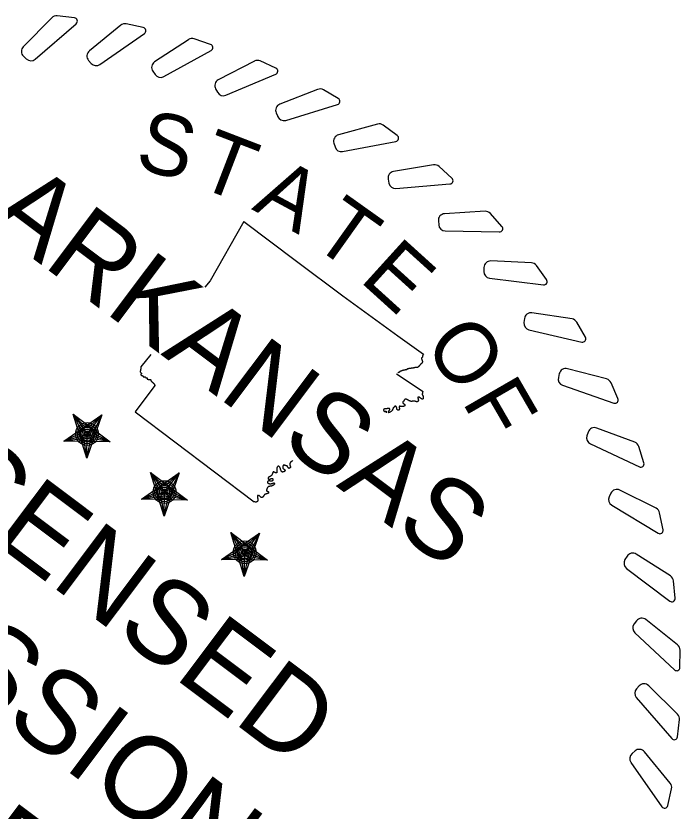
# Model space of a CAD drawing. Extents: x 627721 to 628787, y 367711 to 368404.
# Drawn here: x 628750.25 to 628786.81, y 368199.73 to 368243.51 of the extents above; entities that cross this region are included whole.
import ezdxf

# ---------------------------------------------------------------- set-up
doc = ezdxf.new("R2010")
doc.units = 0
doc.layers.add('R_Border PE-PDH', color=7, linetype='Continuous')

msp = doc.modelspace()

# ---------------------------------------------------------------- linework, layer by layer
at = {"layer": 'R_Border PE-PDH'}
for p, q in [((628771.211, 368223.811), (628772.624, 368222.86)), ((628753.402, 368221.577), (628754.176, 368220.489)), ((628753.402, 368221.577), (628754.041, 368220.892)), ((628753.402, 368221.577), (628753.826, 368220.703)), ((628754.176, 368220.489), (628754.975, 368221.553)), ((628754.975, 368221.553), (628754.304, 368220.909)), ((628754.975, 368221.553), (628754.571, 368220.717)), ((628752.896, 368220.096), (628753.798, 368220.532)), ((628755.431, 368220.053), (628754.49, 368220.537)), ((628752.896, 368220.096), (628754.176, 368220.489)), ((628752.896, 368220.096), (628753.995, 368220.261)), ((628754.147, 368219.157), (628753.989, 368220.252)), ((628754.147, 368219.157), (628754.176, 368220.489)), ((628754.147, 368219.157), (628754.385, 368220.306)), ((628755.431, 368220.053), (628754.176, 368220.489)), ((628755.431, 368220.053), (628754.613, 368220.203)), ((628757.662, 368218.378), (628758.436, 368217.291)), ((628757.662, 368218.378), (628758.301, 368217.693)), ((628757.662, 368218.378), (628758.085, 368217.504)), ((628758.436, 368217.291), (628759.235, 368218.355)), ((628759.235, 368218.355), (628758.564, 368217.71)), ((628759.235, 368218.355), (628758.831, 368217.519)), ((628757.156, 368216.898), (628758.058, 368217.333)), ((628757.156, 368216.898), (628758.436, 368217.291)), ((628757.156, 368216.898), (628758.255, 368217.062)), ((628758.407, 368215.959), (628758.249, 368217.053)), ((628758.407, 368215.959), (628758.436, 368217.291)), ((628758.407, 368215.959), (628758.644, 368217.107)), ((628759.691, 368216.855), (628758.436, 368217.291)), ((628759.691, 368216.855), (628758.75, 368217.338)), ((628759.691, 368216.855), (628758.873, 368217.004)), ((628762.079, 368215.061), (628762.854, 368213.973)), ((628762.079, 368215.061), (628762.718, 368214.376)), ((628762.079, 368215.061), (628762.503, 368214.186)), ((628762.854, 368213.973), (628763.653, 368215.037)), ((628763.653, 368215.037), (628762.982, 368214.392)), ((628763.653, 368215.037), (628763.248, 368214.201)), ((628761.574, 368213.58), (628762.475, 368214.016)), ((628761.574, 368213.58), (628762.854, 368213.973)), ((628762.825, 368212.641), (628762.854, 368213.973)), ((628764.108, 368213.537), (628762.854, 368213.973)), ((628764.108, 368213.537), (628763.167, 368214.021)), ((628761.574, 368213.58), (628762.673, 368213.744)), ((628762.825, 368212.641), (628762.666, 368213.736)), ((628762.825, 368212.641), (628763.062, 368213.789)), ((628764.108, 368213.537), (628763.29, 368213.687))]:
    msp.add_line(p, q, dxfattribs=at)
for points in [[(628752.224, 368243.404), (628750.656, 368241.816)], [(628753.47, 368243.405), (628752.525, 368243.511)], [(628751.314, 368241.134), (628753.569, 368243.085)], [(628756.018, 368243.001), (628754.293, 368241.586)], [(628757.257, 368242.872), (628756.328, 368243.076)], [(628754.875, 368240.839), (628757.322, 368242.543)], [(628759.749, 368242.204), (628757.885, 368240.977)], [(628760.967, 368241.946), (628760.065, 368242.246)], [(628758.386, 368240.173), (628760.998, 368241.612)], [(628750.666, 368241.293), (628750.824, 368241.144)], [(628754.247, 368241.065), (628754.389, 368240.9)], [(628763.376, 368241.022), (628761.394, 368239.996)], [(628764.561, 368240.637), (628763.695, 368241.03)], [(628757.785, 368240.463), (628757.909, 368240.285)], [(628761.808, 368239.144), (628764.556, 368240.302)], [(628761.241, 368239.495), (628761.345, 368239.305)], [(628766.859, 368239.466), (628764.781, 368238.653)], [(628767.998, 368238.96), (628767.178, 368239.441)], [(628765.104, 368237.762), (628767.958, 368238.627)], [(628764.577, 368238.171), (628764.661, 368237.971)], [(628770.161, 368237.555), (628768.009, 368236.964)], [(628771.24, 368236.933), (628770.475, 368237.497)], [(628767.756, 368236.506), (628767.818, 368236.298)], [(628768.238, 368236.044), (628771.166, 368236.606)], [(628773.245, 368235.309), (628771.043, 368234.946)], [(628774.253, 368234.578), (628773.551, 368235.219)], [(628770.743, 368234.517), (628770.784, 368234.304)], [(628771.174, 368234.008), (628774.145, 368234.26)], [(628776.077, 368232.754), (628773.85, 368232.623)], [(628777.004, 368231.921), (628776.372, 368232.631)], [(628762.801, 368232.186), (628760.936, 368228.93), (628760.655, 368228.581)], [(628762.801, 368232.186), (628765.697, 368230.009), (628768.243, 368228.105), (628771.277, 368225.899), (628772.692, 368224.887)], [(628773.507, 368232.227), (628773.524, 368232.011)], [(628773.882, 368231.676), (628776.863, 368231.616)], [(628778.627, 368229.916), (628776.398, 368230.018)], [(628779.461, 368228.99), (628778.908, 368229.763)], [(628776.015, 368229.661), (628776.011, 368229.444)], [(628776.331, 368229.073), (628779.29, 368228.702)], [(628780.866, 368226.827), (628778.66, 368227.162)], [(628778.242, 368226.847), (628778.215, 368226.632)], [(628781.599, 368225.82), (628781.129, 368226.646)], [(628778.495, 368226.229), (628781.398, 368225.551)], [(628757.672, 368224.871), (628757.124, 368224.19)], [(628782.77, 368223.521), (628780.611, 368224.085)], [(628780.163, 368223.815), (628780.113, 368223.604)], [(628757.898, 368223.157), (628756.813, 368221.705), (628763.372, 368216.763)], [(628780.349, 368223.174), (628783.166, 368222.196)], [(628783.394, 368222.442), (628783.013, 368223.314)], [(628754.975, 368221.553), (628754.147, 368219.157), (628753.402, 368221.577), (628755.431, 368220.053), (628752.896, 368220.096), (628754.975, 368221.553)], [(628781.756, 368220.599), (628781.684, 368220.394)], [(628784.318, 368220.034), (628782.23, 368220.821)], [(628781.874, 368219.942), (628784.573, 368218.675)], [(628784.826, 368218.896), (628784.538, 368219.802)], [(628759.235, 368218.355), (628758.407, 368215.959), (628757.662, 368218.378), (628759.691, 368216.855), (628757.156, 368216.898), (628759.235, 368218.355)], [(628783.004, 368217.234), (628782.911, 368217.038)], [(628785.493, 368216.405), (628783.499, 368217.405)], [(628783.053, 368216.569), (628785.605, 368215.027)], [(628785.879, 368215.22), (628785.688, 368216.151)], [(628763.653, 368215.037), (628762.825, 368212.641), (628762.079, 368215.061), (628764.108, 368213.537), (628761.574, 368213.58), (628763.653, 368215.037)], [(628783.893, 368213.757), (628783.781, 368213.572)], [(628786.282, 368212.672), (628784.403, 368213.876)], [(628783.873, 368213.09), (628786.25, 368211.29)], [(628786.542, 368211.454), (628786.449, 368212.4)], [(628784.414, 368210.207), (628784.283, 368210.034)], [(628786.677, 368208.878), (628784.934, 368210.271)], [(628784.324, 368209.546), (628786.5, 368207.506)], [(628786.808, 368207.639), (628786.815, 368208.589)], [(628784.562, 368206.621), (628784.413, 368206.463)], [(628786.673, 368205.063), (628785.085, 368206.63)], [(628784.403, 368205.973), (628786.354, 368203.717)], [(628786.674, 368203.817), (628786.78, 368204.762)], [(628784.333, 368203.039), (628784.169, 368202.898)], [(628786.27, 368201.269), (628784.855, 368202.994)], [(628784.108, 368202.411), (628785.812, 368199.965)], [(628786.141, 368200.03), (628786.345, 368200.958)]]:
    msp.add_lwpolyline(points, dxfattribs=at)
for centre, radius in [((628754.171, 368220.489), 0.628), ((628754.171, 368220.489), 0.527), ((628754.171, 368220.489), 0.422), ((628754.171, 368220.489), 0.361), ((628754.171, 368220.489), 0.272), ((628754.171, 368220.489), 0.181), ((628754.171, 368220.489), 0.108), ((628758.431, 368217.29), 0.628), ((628758.431, 368217.29), 0.527), ((628758.431, 368217.29), 0.422), ((628758.431, 368217.29), 0.361), ((628758.431, 368217.29), 0.272), ((628758.431, 368217.29), 0.181), ((628758.431, 368217.29), 0.108), ((628762.849, 368213.973), 0.628), ((628762.849, 368213.973), 0.527), ((628762.849, 368213.973), 0.422), ((628762.849, 368213.973), 0.361), ((628762.849, 368213.973), 0.272), ((628762.849, 368213.973), 0.181), ((628762.849, 368213.973), 0.108)]:
    msp.add_circle(centre, radius, dxfattribs=at)
for centre, radius, start, end in [((628752.484, 368243.147), 0.366, 83.609, 135.3653), ((628753.45, 368243.223), 0.183, 310.8578, 83.609), ((628756.25, 368242.719), 0.366, 77.609, 129.3653), ((628757.218, 368242.693), 0.183, 304.8578, 77.609), ((628759.95, 368241.899), 0.366, 71.609, 123.3653), ((628750.917, 368241.559), 0.366, 135.3653, 226.7231), ((628754.525, 368241.303), 0.366, 129.3653, 220.7231), ((628760.91, 368241.772), 0.183, 298.8578, 71.609), ((628751.074, 368241.411), 0.366, 226.7231, 310.8578), ((628754.666, 368241.139), 0.366, 220.7231, 304.8578), ((628758.086, 368240.671), 0.366, 123.3653, 214.7231), ((628763.544, 368240.697), 0.366, 65.609, 117.3653), ((628758.21, 368240.493), 0.366, 214.7231, 298.8578), ((628764.485, 368240.471), 0.183, 292.8578, 65.609), ((628761.562, 368239.671), 0.366, 117.3653, 208.7231), ((628766.992, 368239.125), 0.366, 59.609, 111.3653), ((628761.666, 368239.481), 0.366, 208.7231, 292.8578), ((628767.905, 368238.802), 0.183, 286.8578, 59.609), ((628764.914, 368238.312), 0.366, 111.3653, 202.7231), ((628764.998, 368238.113), 0.366, 202.7231, 286.8578), ((628770.258, 368237.202), 0.366, 53.609, 105.3653), ((628768.106, 368236.611), 0.366, 105.3653, 196.7231), ((628771.132, 368236.786), 0.183, 280.8578, 53.609), ((628768.169, 368236.403), 0.366, 196.7231, 280.8578), ((628773.305, 368234.948), 0.366, 47.609, 99.3653), ((628771.103, 368234.585), 0.366, 99.3653, 190.7231), ((628774.13, 368234.443), 0.183, 274.8578, 47.609), ((628771.143, 368234.372), 0.366, 190.7231, 274.8578), ((628773.871, 368232.257), 0.366, 93.3653, 184.7231), ((628776.099, 368232.388), 0.366, 41.609, 93.3653), ((628773.889, 368232.041), 0.366, 184.7231, 268.8578), ((628776.867, 368231.799), 0.183, 268.8578, 41.609), ((628776.381, 368229.653), 0.366, 87.3653, 178.7231), ((628778.61, 368229.55), 0.366, 35.609, 87.3653), ((628776.376, 368229.436), 0.366, 178.7231, 262.8578), ((628779.313, 368228.884), 0.183, 262.8578, 35.609), ((628778.605, 368226.8), 0.366, 81.3653, 172.7231), ((628780.811, 368226.465), 0.366, 29.609, 81.3653), ((628778.578, 368226.585), 0.366, 172.7231, 256.8578), ((628781.44, 368225.729), 0.183, 256.8578, 29.609), ((628780.519, 368223.731), 0.366, 75.3653, 166.7231), ((628780.469, 368223.52), 0.366, 166.7231, 250.8578), ((628782.678, 368223.167), 0.366, 23.609, 75.3653), ((628783.226, 368222.369), 0.183, 250.8578, 23.609), ((628782.101, 368220.478), 0.366, 69.3653, 160.7231), ((628782.029, 368220.274), 0.366, 160.7231, 244.8578), ((628784.189, 368219.692), 0.366, 17.609, 69.3653), ((628784.651, 368218.841), 0.183, 244.8578, 17.609), ((628783.335, 368217.078), 0.366, 63.3653, 154.7231), ((628783.242, 368216.882), 0.366, 154.7231, 238.8578), ((628785.329, 368216.078), 0.366, 11.609, 63.3653), ((628785.7, 368215.183), 0.183, 238.8578, 11.609), ((628784.093, 368213.382), 0.366, 148.7231, 232.8578), ((628784.206, 368213.567), 0.366, 57.3653, 148.7231), ((628786.085, 368212.364), 0.366, 5.609, 57.3653), ((628786.36, 368211.436), 0.183, 232.8578, 5.609), ((628784.574, 368209.813), 0.366, 142.7231, 226.8578), ((628784.706, 368209.985), 0.366, 51.3653, 142.7231), ((628786.449, 368208.592), 0.366, 359.609, 51.3653), ((628786.625, 368207.64), 0.183, 226.8578, 359.609), ((628784.828, 368206.37), 0.366, 45.3653, 136.7231), ((628784.68, 368206.212), 0.366, 136.7231, 220.8578), ((628786.416, 368204.802), 0.366, 353.609, 45.3653), ((628786.492, 368203.837), 0.183, 220.8578, 353.609), ((628784.572, 368202.762), 0.366, 39.3653, 130.7231), ((628784.408, 368202.621), 0.366, 130.7231, 214.8578), ((628785.987, 368201.037), 0.366, 347.609, 39.3653), ((628785.962, 368200.069), 0.183, 214.8578, 347.609)]:
    msp.add_arc(centre, radius, start, end, dxfattribs=at)
for points in [[(628772.692, 368224.887), (628772.674, 368224.86), (628772.657, 368224.831), (628772.642, 368224.802), (628772.632, 368224.784), (628772.641, 368224.76), (628772.636, 368224.742), (628772.627, 368224.713), (628772.587, 368224.696), (628772.583, 368224.664), (628772.581, 368224.645), (628772.584, 368224.627), (628772.589, 368224.609), (628772.596, 368224.584), (628772.61, 368224.563), (628772.617, 368224.538), (628772.625, 368224.509), (628772.63, 368224.482), (628772.625, 368224.451), (628772.62, 368224.423), (628772.607, 368224.4), (628772.59, 368224.382), (628772.571, 368224.363), (628772.546, 368224.35), (628772.528, 368224.33), (628772.509, 368224.308), (628772.492, 368224.284), (628772.472, 368224.262), (628772.455, 368224.244), (628772.437, 368224.225), (628772.419, 368224.207), (628772.403, 368224.19), (628772.388, 368224.172), (628772.367, 368224.159), (628772.343, 368224.146), (628772.316, 368224.148), (628772.29, 368224.147), (628772.268, 368224.146), (628772.247, 368224.147), (628772.225, 368224.146), (628772.203, 368224.144), (628772.181, 368224.141), (628772.159, 368224.136), (628772.139, 368224.132), (628772.122, 368224.119), (628772.102, 368224.117), (628772.076, 368224.114), (628772.05, 368224.112), (628772.023, 368224.109), (628771.997, 368224.106), (628771.97, 368224.103), (628771.943, 368224.099), (628771.921, 368224.096), (628771.898, 368224.092), (628771.876, 368224.088), (628771.85, 368224.083), (628771.825, 368224.075), (628771.801, 368224.066), (628771.778, 368224.058), (628771.765, 368224.029), (628771.741, 368224.024), (628771.718, 368224.019), (628771.694, 368224.02), (628771.67, 368224.016), (628771.651, 368224.012), (628771.631, 368224.008), (628771.611, 368224.004), (628771.585, 368223.999), (628771.558, 368223.993), (628771.532, 368223.988), (628771.51, 368223.983), (628771.494, 368223.964), (628771.474, 368223.956), (628771.448, 368223.944), (628771.417, 368223.944), (628771.391, 368223.931), (628771.371, 368223.921), (628771.361, 368223.895), (628771.342, 368223.884), (628771.324, 368223.874), (628771.301, 368223.87), (628771.283, 368223.861), (628771.28, 368223.86), (628771.274, 368223.859), (628771.275, 368223.855)], [(628757.124, 368224.19), (628757.137, 368224.15), (628757.132, 368224.118), (628757.125, 368224.083), (628757.12, 368224.061), (628757.115, 368224.04), (628757.11, 368224.018), (628757.104, 368223.99), (628757.097, 368223.962), (628757.094, 368223.933), (628757.091, 368223.911), (628757.109, 368223.892), (628757.119, 368223.874), (628757.13, 368223.855), (628757.154, 368223.844), (628757.165, 368223.826), (628757.177, 368223.804), (628757.115, 368223.778), (628757.13, 368223.757), (628757.143, 368223.739), (628757.163, 368223.725), (628757.182, 368223.715), (628757.198, 368223.706), (628757.219, 368223.704), (628757.235, 368223.695), (628757.256, 368223.683), (628757.261, 368223.648), (628757.282, 368223.634), (628757.307, 368223.618), (628757.351, 368223.646), (628757.377, 368223.63), (628757.389, 368223.623), (628757.392, 368223.601), (628757.404, 368223.593), (628757.422, 368223.58), (628757.456, 368223.588), (628757.472, 368223.575), (628757.487, 368223.563), (628757.47, 368223.52), (628757.488, 368223.513), (628757.514, 368223.504), (628757.548, 368223.495), (628757.577, 368223.491), (628757.606, 368223.487), (628757.643, 368223.493), (628757.668, 368223.485), (628757.691, 368223.476), (628757.678, 368223.422), (628757.697, 368223.404), (628757.712, 368223.389), (628757.732, 368223.373), (628757.748, 368223.357), (628757.768, 368223.337), (628757.788, 368223.318), (628757.808, 368223.298), (628757.823, 368223.283), (628757.843, 368223.272), (628757.857, 368223.255), (628757.872, 368223.239), (628757.877, 368223.217), (628757.886, 368223.197), (628757.894, 368223.181), (628757.907, 368223.144), (628757.903, 368223.148), (628757.902, 368223.149), (628757.9, 368223.154), (628757.898, 368223.157)], [(628772.603, 368222.873), (628772.609, 368222.868), (628772.618, 368222.866), (628772.624, 368222.86), (628772.649, 368222.832), (628772.638, 368222.787), (628772.636, 368222.749), (628772.635, 368222.724), (628772.621, 368222.701), (628772.623, 368222.676), (628772.624, 368222.654), (628772.631, 368222.635), (628772.639, 368222.615), (628772.647, 368222.597), (628772.667, 368222.585), (628772.672, 368222.566), (628772.678, 368222.544), (628772.676, 368222.522), (628772.675, 368222.499), (628772.674, 368222.477), (628772.671, 368222.456), (628772.665, 368222.437), (628772.66, 368222.421), (628772.642, 368222.404), (628772.623, 368222.407), (628772.599, 368222.409), (628772.588, 368222.431), (628772.57, 368222.441), (628772.549, 368222.452), (628772.528, 368222.462), (628772.507, 368222.474), (628772.488, 368222.484), (628772.478, 368222.509), (628772.455, 368222.516), (628772.431, 368222.523), (628772.393, 368222.528), (628772.385, 368222.512), (628772.376, 368222.494), (628772.385, 368222.461), (628772.388, 368222.434), (628772.392, 368222.405), (628772.405, 368222.381), (628772.406, 368222.35), (628772.408, 368222.328), (628772.399, 368222.305), (628772.384, 368222.291), (628772.369, 368222.277), (628772.345, 368222.263), (628772.321, 368222.266), (628772.294, 368222.269), (628772.27, 368222.277), (628772.245, 368222.284), (628772.221, 368222.29), (628772.197, 368222.299), (628772.173, 368222.304), (628772.146, 368222.311), (628772.118, 368222.304), (628772.091, 368222.299), (628772.071, 368222.296), (628772.056, 368222.27), (628772.036, 368222.275), (628772.012, 368222.281), (628771.99, 368222.29), (628771.967, 368222.299), (628771.944, 368222.308), (628771.921, 368222.316), (628771.898, 368222.326), (628771.879, 368222.335), (628771.862, 368222.348), (628771.844, 368222.358), (628771.822, 368222.37), (628771.801, 368222.381), (628771.778, 368222.391), (628771.755, 368222.401), (628771.732, 368222.408), (628771.703, 368222.405), (628771.678, 368222.403), (628771.658, 368222.393), (628771.644, 368222.376), (628771.627, 368222.355), (628771.617, 368222.328), (628771.602, 368222.305), (628771.586, 368222.28), (628771.551, 368222.27), (628771.547, 368222.236), (628771.544, 368222.206), (628771.571, 368222.188), (628771.589, 368222.168), (628771.604, 368222.153), (628771.625, 368222.144), (628771.64, 368222.128), (628771.656, 368222.11), (628771.669, 368222.089), (628771.67, 368222.063), (628771.67, 368222.045), (628771.65, 368222.033), (628771.635, 368222.028), (628771.61, 368222.019), (628771.586, 368222.01), (628771.559, 368222.006), (628771.534, 368222.002), (628771.51, 368221.999), (628771.485, 368222), (628771.464, 368222.001), (628771.446, 368222.012), (628771.425, 368222.014), (628771.401, 368222.016), (628771.375, 368222.016), (628771.356, 368222.007), (628771.342, 368222.001), (628771.34, 368221.976), (628771.342, 368221.959), (628771.344, 368221.939), (628771.359, 368221.925), (628771.361, 368221.906), (628771.363, 368221.884), (628771.362, 368221.863), (628771.357, 368221.844), (628771.353, 368221.829), (628771.343, 368221.814), (628771.325, 368221.809), (628771.301, 368221.803), (628771.28, 368221.806), (628771.262, 368221.815), (628771.245, 368221.823), (628771.23, 368221.841), (628771.223, 368221.86), (628771.215, 368221.884), (628771.234, 368221.91), (628771.223, 368221.931), (628771.214, 368221.946), (628771.203, 368221.96), (628771.194, 368221.975), (628771.186, 368221.988), (628771.181, 368222.004), (628771.172, 368222.016), (628771.162, 368222.031), (628771.138, 368222.029), (628771.115, 368222.023), (628771.09, 368222.015), (628771.091, 368221.985), (628771.076, 368221.971), (628771.059, 368221.954), (628771.029, 368221.948), (628771.02, 368221.926), (628771.013, 368221.909), (628771.008, 368221.892), (628771.002, 368221.875), (628770.993, 368221.852), (628770.985, 368221.829), (628770.975, 368221.806), (628770.968, 368221.789), (628770.954, 368221.777), (628770.941, 368221.764), (628770.922, 368221.746), (628770.902, 368221.73), (628770.881, 368221.714), (628770.857, 368221.697), (628770.831, 368221.685), (628770.803, 368221.674), (628770.787, 368221.668), (628770.747, 368221.665), (628770.753, 368221.681), (628770.762, 368221.708), (628770.776, 368221.734), (628770.789, 368221.76), (628770.8, 368221.781), (628770.814, 368221.8), (628770.824, 368221.821), (628770.831, 368221.836), (628770.831, 368221.852), (628770.827, 368221.87), (628770.823, 368221.882), (628770.811, 368221.891), (628770.799, 368221.893), (628770.78, 368221.895), (628770.761, 368221.897), (628770.741, 368221.894), (628770.717, 368221.891), (628770.693, 368221.887), (628770.669, 368221.884), (628770.641, 368221.881), (628770.613, 368221.881), (628770.584, 368221.878), (628770.561, 368221.876), (628770.538, 368221.867), (628770.52, 368221.856), (628770.5, 368221.845), (628770.488, 368221.819), (628770.494, 368221.789), (628770.498, 368221.767), (628770.509, 368221.754), (628770.523, 368221.745), (628770.533, 368221.737), (628770.546, 368221.734), (628770.561, 368221.733), (628770.579, 368221.731), (628770.589, 368221.755), (628770.604, 368221.756), (628770.616, 368221.758), (628770.638, 368221.752), (628770.639, 368221.739), (628770.64, 368221.713), (628770.635, 368221.687), (628770.626, 368221.662)], [(628765.5, 368219.027), (628765.487, 368219.015), (628765.467, 368219.009), (628765.451, 368218.999), (628765.426, 368218.981), (628765.4, 368218.963), (628765.378, 368218.942), (628765.359, 368218.925), (628765.347, 368218.901), (628765.337, 368218.877), (628765.328, 368218.854), (628765.321, 368218.83), (628765.325, 368218.805), (628765.329, 368218.783), (628765.341, 368218.765), (628765.347, 368218.744), (628765.354, 368218.719), (628765.36, 368218.693), (628765.362, 368218.668), (628765.365, 368218.642), (628765.339, 368218.617), (628765.312, 368218.608), (628765.297, 368218.602), (628765.279, 368218.596), (628765.267, 368218.605), (628765.246, 368218.619), (628765.231, 368218.646), (628765.217, 368218.668), (628765.205, 368218.686), (628765.201, 368218.712), (628765.185, 368218.726), (628765.172, 368218.736), (628765.152, 368218.739), (628765.134, 368218.744), (628765.109, 368218.75), (628765.083, 368218.753), (628765.058, 368218.759), (628765.042, 368218.763), (628765.031, 368218.784), (628765.013, 368218.784), (628764.975, 368218.786), (628764.954, 368218.733), (628764.95, 368218.697), (628764.947, 368218.663), (628764.938, 368218.622), (628764.96, 368218.594), (628764.973, 368218.578), (628764.993, 368218.571), (628765.008, 368218.558), (628765.026, 368218.543), (628765.049, 368218.534), (628765.059, 368218.509), (628765.071, 368218.479), (628765.05, 368218.446), (628765.03, 368218.43), (628765.011, 368218.415), (628764.989, 368218.403), (628764.957, 368218.4), (628764.927, 368218.397), (628764.898, 368218.396), (628764.883, 368218.414), (628764.864, 368218.436), (628764.85, 368218.466), (628764.839, 368218.497), (628764.831, 368218.521), (628764.824, 368218.544), (628764.817, 368218.568), (628764.809, 368218.591), (628764.802, 368218.613), (628764.792, 368218.636), (628764.782, 368218.662), (628764.762, 368218.68), (628764.744, 368218.698), (628764.733, 368218.708), (628764.723, 368218.718), (628764.704, 368218.716), (628764.662, 368218.712), (628764.644, 368218.681), (628764.632, 368218.653), (628764.62, 368218.626), (628764.609, 368218.597), (628764.609, 368218.564), (628764.609, 368218.534), (628764.619, 368218.51), (628764.621, 368218.482), (628764.623, 368218.451), (628764.622, 368218.419), (628764.618, 368218.389), (628764.616, 368218.371), (628764.598, 368218.349), (628764.577, 368218.35), (628764.561, 368218.35), (628764.549, 368218.356), (628764.535, 368218.361), (628764.513, 368218.37), (628764.492, 368218.383), (628764.469, 368218.392), (628764.454, 368218.397), (628764.439, 368218.401), (628764.421, 368218.399), (628764.413, 368218.399), (628764.404, 368218.398), (628764.402, 368218.392), (628764.39, 368218.368), (628764.384, 368218.342), (628764.374, 368218.317), (628764.363, 368218.291), (628764.352, 368218.265), (628764.34, 368218.239), (628764.331, 368218.22), (628764.32, 368218.199), (628764.302, 368218.189), (628764.284, 368218.178), (628764.266, 368218.168), (628764.248, 368218.157), (628764.22, 368218.141), (628764.191, 368218.124), (628764.163, 368218.108), (628764.147, 368218.098), (628764.136, 368218.08), (628764.132, 368218.059), (628764.129, 368218.045), (628764.13, 368218.031), (628764.137, 368218.021), (628764.144, 368218.013), (628764.158, 368218.01), (628764.17, 368218.008), (628764.188, 368218.006), (628764.206, 368218.004), (628764.224, 368218.006), (628764.24, 368218.009), (628764.254, 368218.013), (628764.269, 368218.018), (628764.285, 368218.023), (628764.298, 368218.034), (628764.316, 368218.039), (628764.337, 368218.044), (628764.36, 368218.047), (628764.376, 368218.041), (628764.394, 368218.034), (628764.401, 368218.006), (628764.403, 368217.979), (628764.404, 368217.95), (628764.389, 368217.929), (628764.372, 368217.915), (628764.354, 368217.902), (628764.334, 368217.889), (628764.308, 368217.887), (628764.289, 368217.886), (628764.272, 368217.89), (628764.255, 368217.894), (628764.234, 368217.898), (628764.216, 368217.908), (628764.195, 368217.911), (628764.172, 368217.914), (628764.149, 368217.908), (628764.131, 368217.897), (628764.115, 368217.888), (628764.106, 368217.866), (628764.105, 368217.844), (628764.104, 368217.827), (628764.103, 368217.81), (628764.113, 368217.799), (628764.131, 368217.778), (628764.162, 368217.77), (628764.189, 368217.761), (628764.208, 368217.755), (628764.228, 368217.745), (628764.248, 368217.747), (628764.263, 368217.749), (628764.278, 368217.752), (628764.292, 368217.754), (628764.31, 368217.756), (628764.328, 368217.759), (628764.346, 368217.761), (628764.36, 368217.763), (628764.371, 368217.774), (628764.385, 368217.78), (628764.4, 368217.786), (628764.415, 368217.791), (628764.432, 368217.794), (628764.45, 368217.798), (628764.474, 368217.789), (628764.48, 368217.772), (628764.485, 368217.759), (628764.486, 368217.743), (628764.48, 368217.731), (628764.468, 368217.708), (628764.448, 368217.689), (628764.427, 368217.675), (628764.405, 368217.661), (628764.383, 368217.647), (628764.359, 368217.637), (628764.335, 368217.627), (628764.312, 368217.619), (628764.288, 368217.614), (628764.267, 368217.609), (628764.246, 368217.612), (628764.225, 368217.608), (628764.188, 368217.601), (628764.149, 368217.594), (628764.123, 368217.57), (628764.103, 368217.551), (628764.092, 368217.521), (628764.081, 368217.495), (628764.072, 368217.472), (628764.064, 368217.449), (628764.057, 368217.426), (628764.051, 368217.406), (628764.039, 368217.381), (628764.05, 368217.364), (628764.06, 368217.348), (628764.084, 368217.349), (628764.1, 368217.341), (628764.118, 368217.331), (628764.137, 368217.322), (628764.152, 368217.31), (628764.164, 368217.3), (628764.165, 368217.281), (628764.163, 368217.265), (628764.161, 368217.243), (628764.142, 368217.223), (628764.122, 368217.217), (628764.098, 368217.21), (628764.074, 368217.203), (628764.05, 368217.196), (628764.027, 368217.189), (628764.004, 368217.182), (628763.981, 368217.175), (628763.954, 368217.166), (628763.931, 368217.146), (628763.915, 368217.124), (628763.904, 368217.109), (628763.898, 368217.089), (628763.888, 368217.074), (628763.879, 368217.059), (628763.869, 368217.045), (628763.857, 368217.032), (628763.844, 368217.018), (628763.828, 368217.007), (628763.809, 368216.998), (628763.795, 368216.992), (628763.778, 368216.985), (628763.765, 368216.992), (628763.741, 368217.005), (628763.721, 368217.026), (628763.7, 368217.044), (628763.678, 368217.063), (628763.659, 368217.085), (628763.636, 368217.103), (628763.622, 368217.114), (628763.601, 368217.115), (628763.582, 368217.11), (628763.555, 368217.103), (628763.543, 368217.069), (628763.543, 368217.044), (628763.544, 368217.018), (628763.546, 368216.993), (628763.551, 368216.968), (628763.554, 368216.953), (628763.56, 368216.939), (628763.562, 368216.923), (628763.567, 368216.896), (628763.567, 368216.87), (628763.566, 368216.842), (628763.565, 368216.823), (628763.56, 368216.804), (628763.553, 368216.787), (628763.547, 368216.774), (628763.535, 368216.763), (628763.52, 368216.756), (628763.505, 368216.748), (628763.491, 368216.745), (628763.472, 368216.744), (628763.435, 368216.743), (628763.401, 368216.747), (628763.372, 368216.763)]]:
    msp.add_open_spline(points, degree=3, dxfattribs=at)

# ---------------------------------------------------------------- texts
for s, height, rotation, p in [('S', 3.378, 345.9433, (628756.71, 368235.145)), ('T', 3.378, 338.9725, (628760.067, 368234.188)), ('A', 3.378, 331.7613, (628763.188, 368232.878)), ('ARKANSAS', 4.3912, 323.0968, (628748.536, 368232.134)), ('T', 3.378, 324.5497, (628766.412, 368231.006)), ('E', 3.378, 317.8196, (628769.104, 368228.955)), ('O', 3.378, 307.0892, (628772.628, 368225.337)), ('LICENSED', 4.5741, 323.0968, (628741.206, 368220.378)), ('F', 3.378, 300.0113, (628774.774, 368222.289)), ('PROFESSIONAL', 4.57414, 323.0968, (628729.399, 368219.71)), ('ENGINEER', 4.5741, 323.0968, (628731.789, 368208.382))]:
    msp.add_text(s, height=height, rotation=rotation, dxfattribs=at).set_placement(p)

doc.saveas('drawing.dxf')
